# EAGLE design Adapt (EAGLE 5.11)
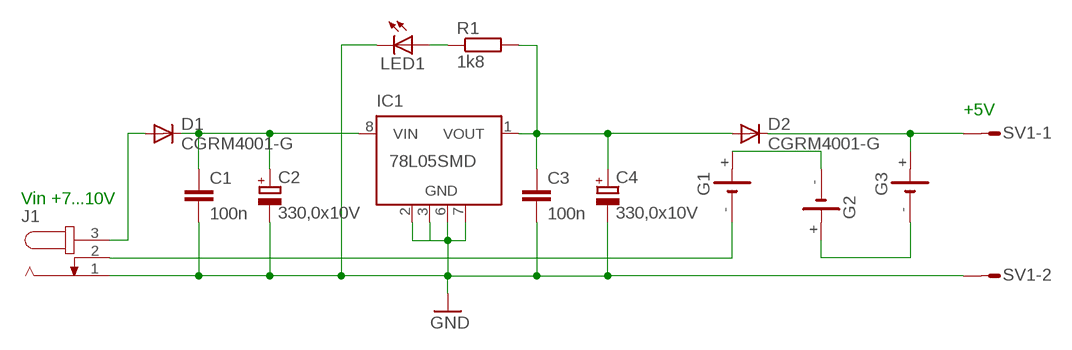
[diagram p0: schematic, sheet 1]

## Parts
C1  100n  C-EUC1206  [C1206]
C2  330,0x10V  CPOL-EU085CS-1AR  [085CS_1AR]
C3  100n  C-EUC1206  [C1206]
C4  330,0x10V  CPOL-EU085CS-1AR  [085CS_1AR]
D1  CGRM4001-G  [SOD-123_MINI-SMA]
D2  CGRM4001-G  [SOD-123_MINI-SMA]
G1  SL-160AA/PR  [SL-160AA/PR]
G2  SL-160AA/PR  [SL-160AA/PR]
G3  SL-160AA/PR  [SL-160AA/PR]
IC1  78L05SMD  [SO08]
J1  JACK-PLUG0  [SPC4077]
LED1  LEDCHIPLED_1206  [CHIPLED_1206]
R1  1k8  R-EU_R1206  [R1206]
SV1  S02P  [S02P]

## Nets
GND: C1.2 C2.- C3.2 C4.- IC1.2(GND) IC1.3(GND) IC1.6(GND) IC1.7(GND) J1.1 LED1.C SV1.2
N$1: C3.1 C4.+ D2.A IC1.1(VOUT) R1.2
N$2: C1.1 C2.+ D1.C IC1.8(VIN)
N$3: D1.A J1.3
N$4: G2.+ G3.-
N$5: D2.C G3.+ SV1.1
N$6: G1.- J1.2
N$7: LED1.A R1.1
N$8: G1.+ G2.-
Unconnected: IC1.4(NC) IC1.5(NC)

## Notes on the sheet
- +5V
- Vin +7...10V

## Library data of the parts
C1 C3 = resistor:C-EU: CAPACITOR, European symbol
C2 C4 = resistor:CPOL-EU: POLARIZED CAPACITOR, European symbol
D1 D2 = diode:CGRM400*-G: Molded plasitc,JEDEC SOD-123/Mini SMA
G1-G3 = battery:SL-160AA/PR: LI BATTERY Sonnenschein
IC1 = linear:78L*SMD: Positive VOLTAGE REGULATOR
J1 = con-jack:JACK-PLUG: DC POWER JACK Power Jack, DC, Right Angle, Through Hole, Rated 5A at 16VDC, PC Terminals Distributor: Farnell (www.Farnell.de) Drawing: 84N1161.pdf / 84N1162.pdf Manufacturer: SPC Technology (www.spctechnology.com) Type: SPC4077 / SPC 4078; OC_FARNELL: unknown; OC_NEWARK: unknown
LED1 = led:LED: LED
R1 = resistor:R-EU_: RESISTOR, European symbol
SV1 = con-amp-mt:S02P: AMP MT CONNECTOR; OC_FARNELL: unknown; OC_NEWARK: unknown

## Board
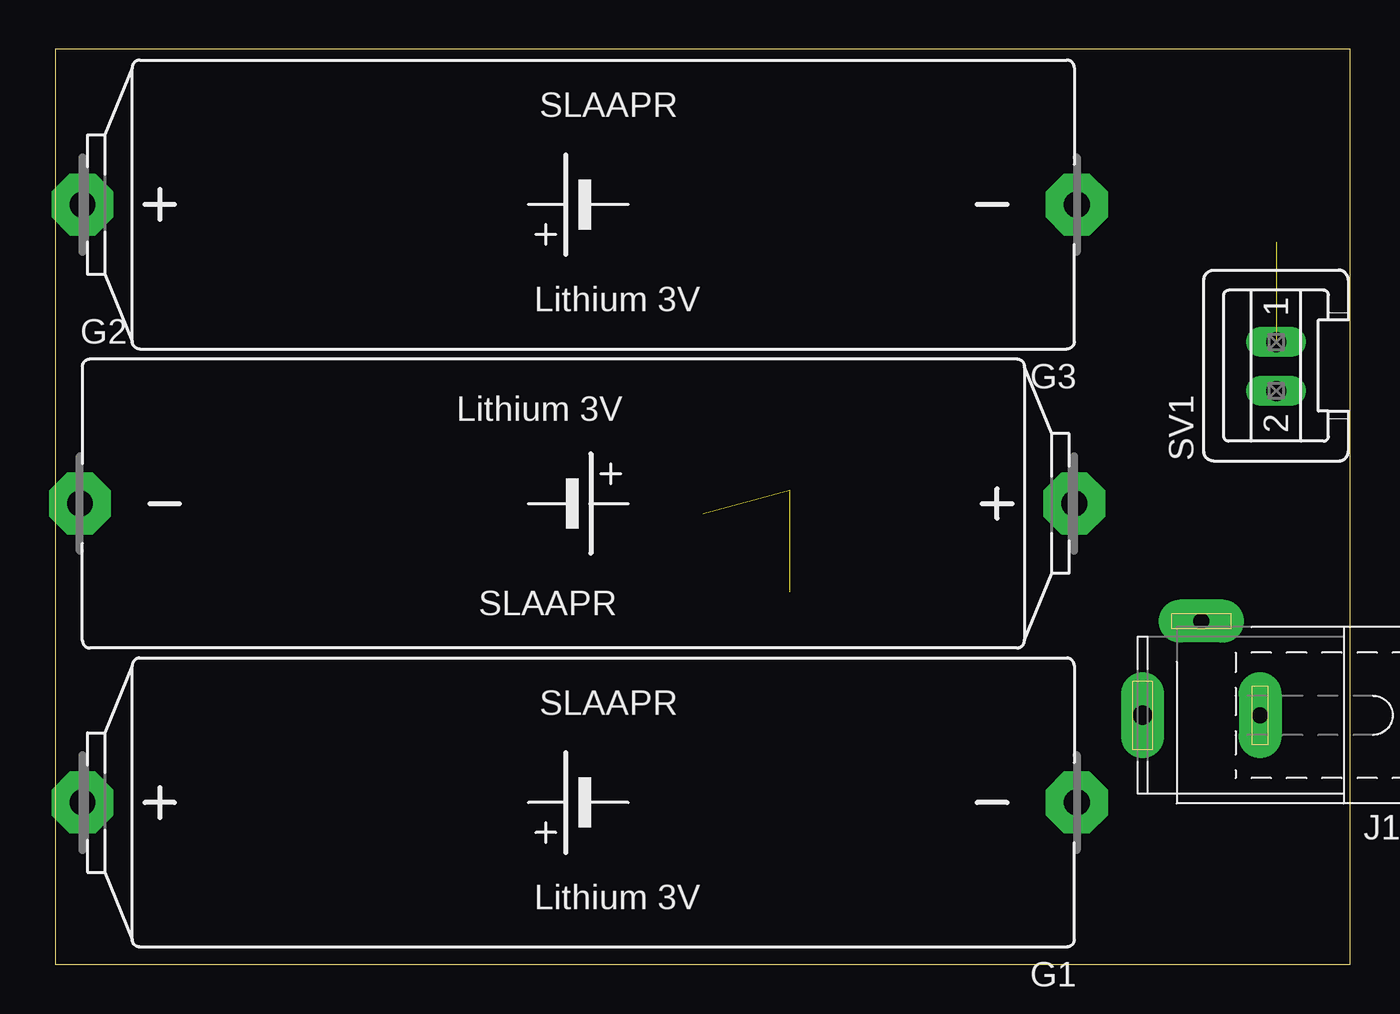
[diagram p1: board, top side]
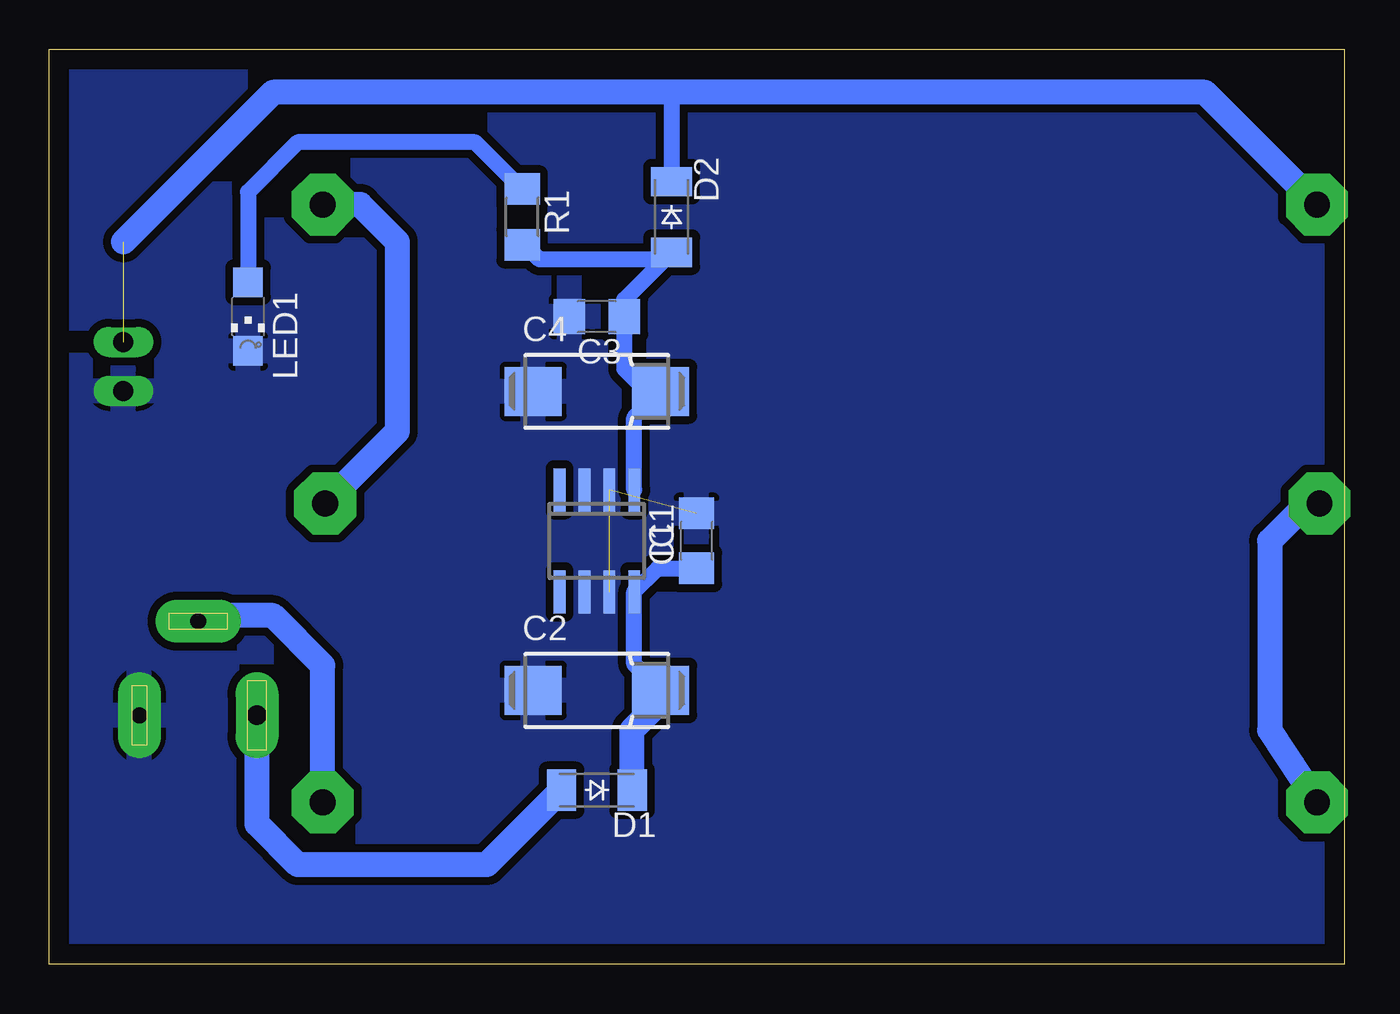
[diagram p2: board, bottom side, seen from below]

Size 66.02 x 46.66 mm. Coordinates in mm from the lower left corner, seen from the top.
Outline: 0,0 66.02,0 66.02,46.66 0,46.66 0,0
Copper layers (1*16): Top 0.035mm / dielectric 1.5mm / Bottom 0.035mm
Design rules "default": minimum track width 10mil, minimum drill 24mil, track to track 8mil, track to pad 8mil, pad to pad 8mil, via to via 8mil, smd to smd 8mil, copper to edge 40mil, drill to drill 8mil, minimum pad ring 10mil, minimum via ring 8mil, stop-mask expansion 4mil, vias tented up to drill 0mil, thermal gap 10mil

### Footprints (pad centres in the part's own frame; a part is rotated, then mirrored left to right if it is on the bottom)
C1206 = smd 1.6 x 1.8: 1 -1.4,0; 2 1.4,0
085CS_1AR = smd 2.9 x 2.5: + 3.25,0; - -3.25,0
SOD-123_MINI-SMA = smd 1.5 x 2.1: A 1.8,0; C -1.8,0
SL-160AA/PR = drill 1.321 pad 3.15 octagon: + 25.273,0; - -25.4,0
SO08 = smd 0.6 x 2.2: 1 -1.905,-2.6; 2 -0.635,-2.6; 3 0.635,-2.6; 4 1.905,-2.6; 5 1.905,2.6; 6 0.635,2.6; 7 -0.635,2.6; 8 -1.905,2.6
SPC4077 = drill 0.8 pad 2.184 long: 1 -3,0; 2 0,-4.8 | drill 1 pad 2.184 long: 3 3,0
CHIPLED_1206 = smd 1.5 x 1.5: A 0,-1.75; C 0,1.75
R1206 = smd 1.6 x 1.803: 1 -1.422,0; 2 1.422,0
S02P = drill 1.016 long: 1 1.25,0; 2 -1.25,0

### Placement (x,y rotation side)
C1  33.02,21.59 90 bottom
C2  38.1,13.97 0 bottom
C3  38.1,33.02 180 bottom
C4  38.1,29.21 0 bottom
D1  38.1,8.89 180 bottom
D2  34.29,38.1 270 bottom
G1  26.67,8.26 180 top
G2  26.67,23.5 0 top
G3  26.67,38.73 180 top
IC1  38.1,21.59 180 bottom
J1  58.42,12.7 180 top
LED1  55.88,33.02 180 bottom
R1  41.91,38.1 270 bottom
SV1  62.23,30.48 90 top

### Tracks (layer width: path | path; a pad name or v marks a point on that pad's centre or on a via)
GND  (2 unrouted)
  Bottom 0.813: C1.2 33.02,22.86
  pour Bottom (isolate 0.406): -1.27,48.26 68.58,48.26 68.58,-2.54 -1.27,-2.54
N$1
  Bottom 0.813: IC1.1 36.2,27.86 35.21,28.86 | 35.21,28.86 C4.+ | 35.21,28.86 36.7,30.35 C3.1 36.7,33.15 | 34.66,35.93 36.7,33.89 36.7,33.15 | 34.66,35.93 D2.A | 36.7,33.15 36.83,33.02 | R1.2 41.91,36.83 41.01,35.93 34.66,35.93
N$2
  Bottom 0.813: C2.+ 36.2,15.31 IC1.8 35,20.19 C1.1
  Bottom 1.27: D1.C 36.3,11.96 34.29,13.97 C2.+
N$3
  Bottom 1.27: J1.3 55.42,7.16 53.34,5.08 43.71,5.08 D1.A
N$4
  Bottom 1.27: G3.- 50.17,38.73 48.26,36.83 48.26,27.18 G2.+
N$5  (1 unrouted)
  Bottom 0.813: 34.29,44.45 D2.C
  Bottom 1.27: G3.+ 7.11,44.45 34.29,44.45 54.61,44.45 62.23,36.83
N$6
  Bottom 1.27: J1.2 58.14,17.78 54.61,17.78 52.07,15.24 G1.-
N$7
  Bottom 0.813: R1.1 44.3,41.91 53.34,41.91 55.88,39.37 LED1.A
N$8
  Bottom 1.27: G2.- 1.91,23.5 3.81,21.59 3.81,11.94 G1.+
